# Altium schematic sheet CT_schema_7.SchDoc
size 274 x 160 mm
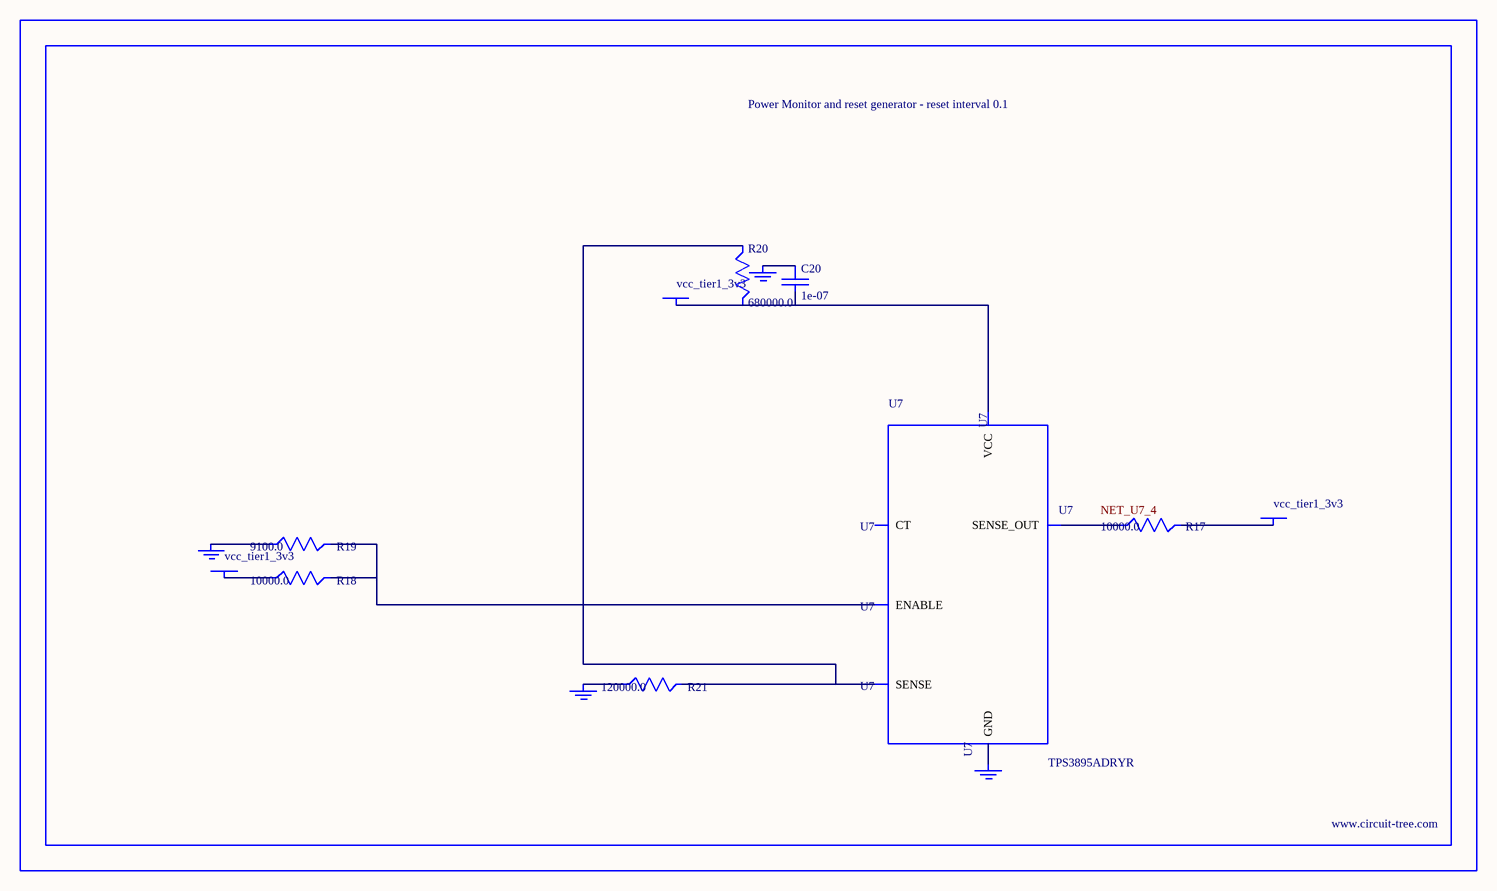
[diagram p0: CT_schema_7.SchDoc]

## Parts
BORDER6  (no value)
C20  1e-07  [C0402]
GND_INSTANCE_6_0  (no value)
GND_INSTANCE_6_1  (no value)
GND_INSTANCE_6_2  (no value)
GND_INSTANCE_6_3  (no value)
POWER_INSTANCE_6_0  vcc_tier1_3v3
POWER_INSTANCE_6_1  vcc_tier1_3v3
POWER_INSTANCE_6_2  vcc_tier1_3v3
R17  10000.0  [R0603]
R18  10000.0  [R0603]
R19  9100.0  [R0603]
R20  680000.0  [R0603]
R21  120000.0  [R0603]
U7  TPS3895ADRYR  [SON-6]

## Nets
NetC20_1: C20.1 GND_INSTANCE_6_2.0(GND)
NetC20_2: C20.2 POWER_INSTANCE_6_2.0(PWR) R20.2 U7.6(VCC)
NetGND_INSTANCE_6_0_0: GND_INSTANCE_6_0.0(GND) R19.1
NetGND_INSTANCE_6_1_0: GND_INSTANCE_6_1.0(GND) R21.1
NetGND_INSTANCE_6_3_0: GND_INSTANCE_6_3.0(GND) U7.2(GND)
NetPOWER_INSTANCE_6_0_0: POWER_INSTANCE_6_0.0(PWR) R18.1
NetPOWER_INSTANCE_6_1_0: POWER_INSTANCE_6_1.0(PWR) R17.2
NetR17_1: R17.1 U7.4(SENSE_OUT)
NetR18_2: R18.2 R19.2 U7.1(ENABLE)
NetR20_1: R20.1 R21.2 U7.3(SENSE)

Not connected (* = marked no-connect by the designer): U7 5(CT)

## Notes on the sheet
- Labels drawn without touching a wire or pin: NET_U7_4

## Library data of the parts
BORDER6 = BORDER_PAGE6
C20 = C0402C104K3RACTU
GND_INSTANCE_6_0-GND_INSTANCE_6_3 = GND
POWER_INSTANCE_6_0-POWER_INSTANCE_6_2 = PWR
R17 R18 = RC0603JR-0710KL
R19 = RC0603JR-079K1L
R20 = RC0603JR-07680KL
R21 = RC0603JR-07120KL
